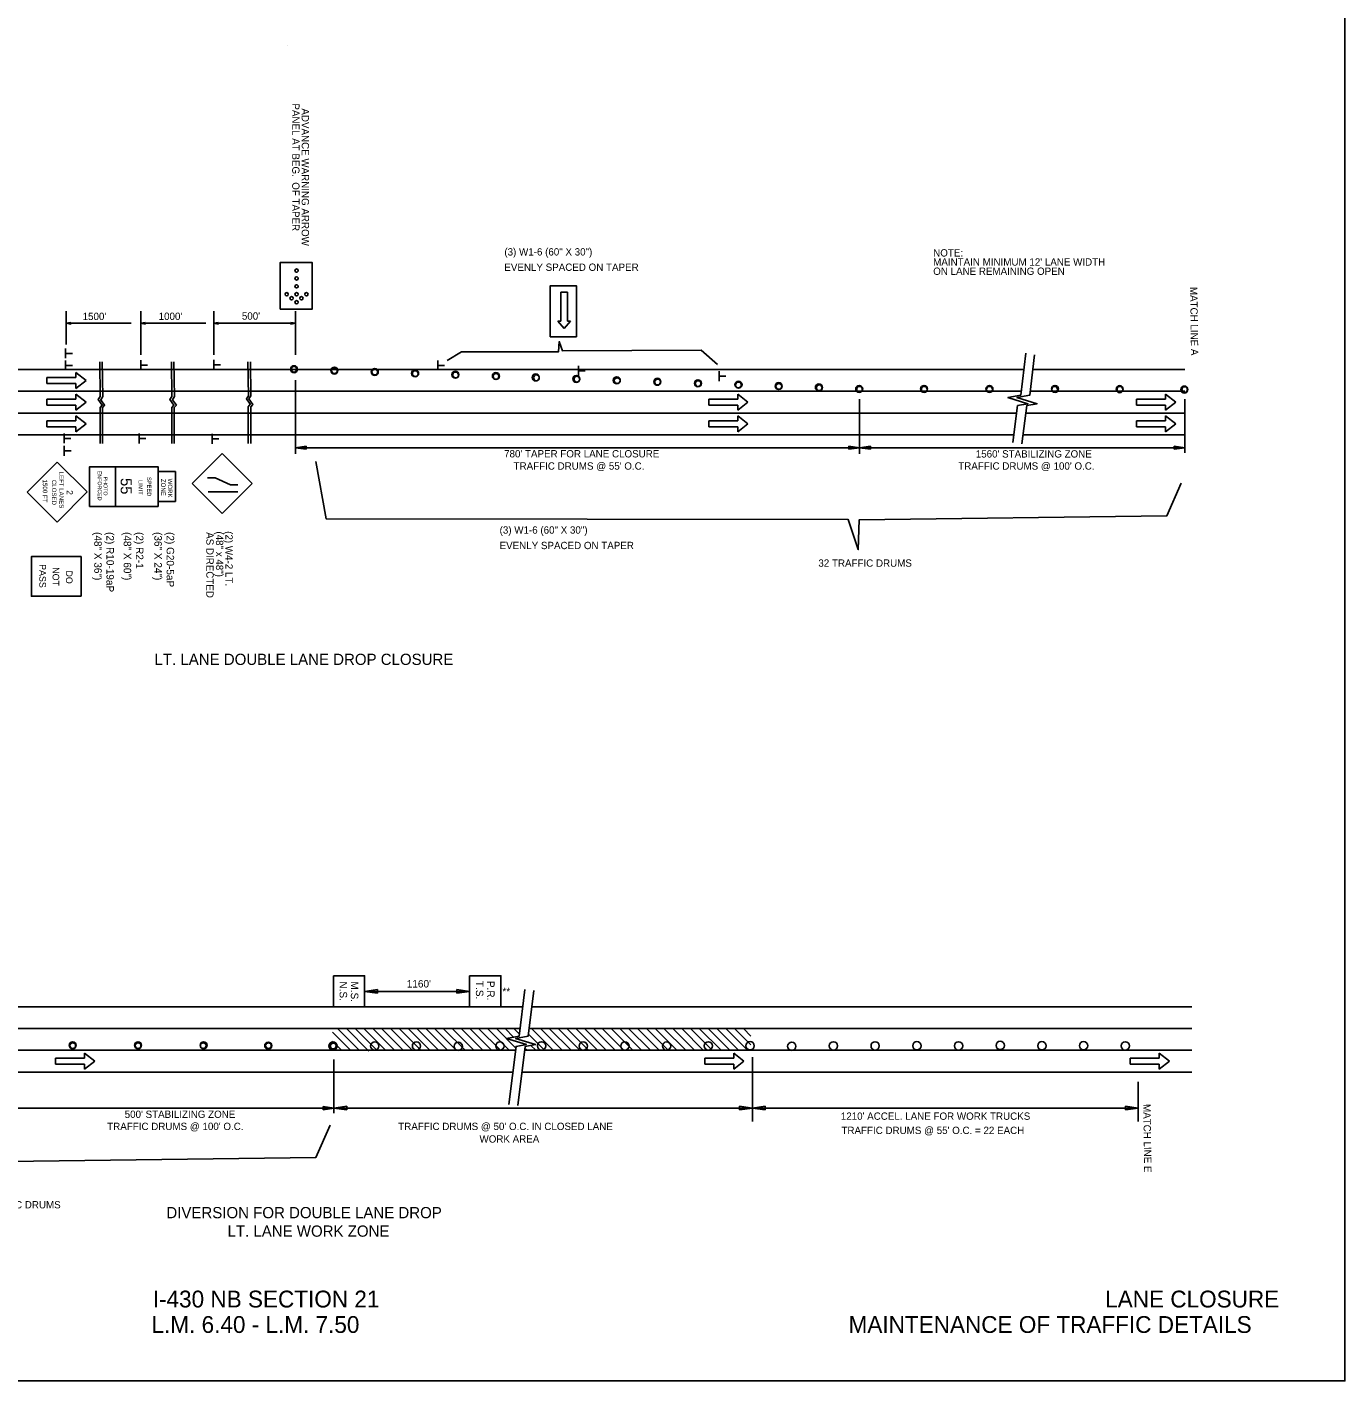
# Model space of a CAD drawing. Extents: x -100 to 745, y -1581 to -107.
# Drawn here: x 639.2 to 744.8, y -706.8 to -598.3 of the extents above; entities that cross this region are included whole.
import ezdxf

# ---------------------------------------------------------------- set-up
doc = ezdxf.new("R2010")
doc.units = 0
for name, color, linetype in [('Default', 7, 'Continuous'), ('R_Border', 7, 'Continuous'), ('R_Proposed Road', 7, 'Continuous'), ('R_ROW', 7, 'Continuous'), ('R_ROW Annot', 7, 'Continuous')]:
    doc.layers.add(name, color=color, linetype=linetype)

msp = doc.modelspace()

# ---------------------------------------------------------------- linework, layer by layer
at = {"layer": 'Default'}
for p, q in [((681.95, -619.54), (681.95, -621.87)), ((681.95, -619.54), (682.47, -619.54)), ((682.47, -619.54), (682.47, -621.87)), ((642.31, -621.05), (642.31, -623.74)), ((648.28, -621.05), (648.28, -624.57)), ((654.13, -621.05), (654.13, -624.57)), ((660.68, -621.05), (660.68, -624.57)), ((642.68, -621.98), (642.31, -622.03)), ((642.31, -622.03), (647.53, -622.03)), ((642.68, -622.09), (642.31, -622.03)), ((642.68, -621.99), (642.37, -622.03)), ((642.68, -622.08), (642.37, -622.03)), ((642.68, -622), (642.43, -622.03)), ((642.68, -622.07), (642.43, -622.03)), ((642.68, -622), (642.5, -622.03)), ((642.68, -622.06), (642.5, -622.03)), ((642.68, -622.01), (642.56, -622.03)), ((642.68, -622.05), (642.56, -622.03)), ((642.68, -622.02), (642.62, -622.03)), ((642.68, -622.04), (642.62, -622.03)), ((642.68, -622.09), (642.68, -621.98)), ((648.65, -621.98), (648.28, -622.03)), ((648.28, -622.03), (653.5, -622.03)), ((648.65, -622.09), (648.28, -622.03)), ((648.65, -621.99), (648.34, -622.03)), ((648.65, -622.08), (648.34, -622.03)), ((648.65, -622), (648.4, -622.03)), ((648.65, -622.07), (648.4, -622.03)), ((648.65, -622), (648.47, -622.03)), ((648.65, -622.06), (648.47, -622.03)), ((648.65, -622.01), (648.53, -622.03)), ((648.65, -622.05), (648.53, -622.03)), ((648.65, -622.02), (648.59, -622.03)), ((648.65, -622.04), (648.59, -622.03)), ((648.65, -622.09), (648.65, -621.98)), ((654.5, -621.98), (654.13, -622.03)), ((654.13, -622.03), (660.68, -622.03)), ((654.5, -622.09), (654.13, -622.03)), ((654.5, -621.99), (654.19, -622.03)), ((654.5, -622.08), (654.19, -622.03)), ((654.5, -622), (654.25, -622.03)), ((654.5, -622.07), (654.25, -622.03)), ((654.5, -622), (654.32, -622.03)), ((654.5, -622.06), (654.32, -622.03)), ((654.5, -622.01), (654.38, -622.03)), ((654.5, -622.05), (654.38, -622.03)), ((654.5, -622.02), (654.44, -622.03)), ((654.5, -622.04), (654.44, -622.03)), ((654.5, -622.09), (654.5, -621.98)), ((660.3, -621.98), (660.68, -622.03)), ((660.3, -621.98), (660.3, -622.09)), ((660.3, -621.99), (660.61, -622.03)), ((660.3, -622), (660.55, -622.03)), ((660.3, -622), (660.49, -622.03)), ((660.3, -622.01), (660.42, -622.03)), ((660.3, -622.02), (660.36, -622.03)), ((660.3, -622.09), (660.68, -622.03)), ((660.3, -622.05), (660.42, -622.03)), ((660.3, -622.07), (660.55, -622.03)), ((660.3, -622.08), (660.61, -622.03)), ((660.3, -622.06), (660.49, -622.03)), ((660.3, -622.04), (660.36, -622.03)), ((681.95, -621.87), (681.7, -621.87)), ((681.7, -621.87), (682.21, -622.44)), ((682.21, -622.44), (682.73, -621.87)), ((682.47, -621.87), (682.73, -621.87)), ((642.27, -624.82), (642.27, -624.04)), ((642.28, -624.44), (642.82, -624.44)), ((636.02, -625.74), (644.68, -625.74)), ((642.27, -625.79), (642.27, -625.01)), ((642.28, -625.4), (642.81, -625.4)), ((643.09, -625.98), (643.09, -626.38)), ((643.09, -625.98), (643.91, -626.61)), ((644.68, -625.74), (660.68, -625.74)), ((648.28, -625.77), (648.28, -624.99)), ((648.29, -625.38), (648.82, -625.38)), ((654.13, -625.75), (654.13, -624.97)), ((654.14, -625.36), (654.67, -625.36)), ((660.68, -625.74), (719.03, -625.74)), ((672.08, -625.02), (672.08, -625.8)), ((672.09, -625.41), (672.62, -625.41)), ((683.35, -625.45), (683.35, -626.23)), ((683.36, -625.84), (683.89, -625.84)), ((694.62, -625.88), (694.62, -626.66)), ((719.76, -625.74), (731.95, -625.74)), ((643.09, -626.38), (640.76, -626.38)), ((640.76, -626.38), (640.76, -626.85)), ((643.09, -626.85), (640.76, -626.85)), ((643.91, -626.61), (643.09, -627.25)), ((643.09, -626.85), (643.09, -627.25)), ((660.68, -626.59), (660.68, -632.5)), ((694.63, -626.26), (695.16, -626.26)), ((636.02, -627.48), (644.68, -627.48)), ((643.09, -628.12), (640.76, -628.12)), ((640.76, -628.12), (640.76, -628.59)), ((643.09, -627.72), (643.09, -628.12)), ((643.09, -627.72), (643.91, -628.35)), ((644.68, -627.48), (660.68, -627.48)), ((660.68, -627.48), (718.82, -627.48)), ((696.12, -628.12), (693.79, -628.12)), ((693.79, -628.59), (693.79, -628.12)), ((696.12, -628.12), (696.12, -627.72)), ((696.94, -628.35), (696.12, -627.72)), ((705.88, -632.5), (705.88, -628.11)), ((719.55, -627.48), (731.95, -627.48)), ((730.39, -628.12), (728.07, -628.12)), ((728.07, -628.59), (728.07, -628.12)), ((730.39, -628.12), (730.39, -627.72)), ((731.21, -628.35), (730.39, -627.72)), ((731.95, -632.41), (731.95, -628.11)), ((636.02, -629.22), (644.68, -629.22)), ((643.09, -628.59), (640.76, -628.59)), ((643.91, -628.35), (643.09, -628.98)), ((643.09, -628.59), (643.09, -628.98)), ((644.68, -629.22), (660.68, -629.22)), ((660.68, -629.22), (718.47, -629.22)), ((696.12, -628.59), (693.79, -628.59)), ((696.12, -628.98), (696.94, -628.35)), ((696.12, -628.98), (696.12, -628.59)), ((719.2, -629.22), (731.95, -629.22)), ((730.39, -628.59), (728.07, -628.59)), ((730.39, -628.98), (731.21, -628.35)), ((730.39, -628.98), (730.39, -628.59)), ((643.09, -629.85), (640.76, -629.85)), ((640.76, -629.85), (640.76, -630.33)), ((643.09, -630.33), (640.76, -630.33)), ((643.09, -629.46), (643.09, -629.85)), ((643.09, -629.46), (643.91, -630.09)), ((643.91, -630.09), (643.09, -630.72)), ((643.09, -630.33), (643.09, -630.72)), ((696.12, -629.85), (693.79, -629.85)), ((693.79, -630.33), (693.79, -629.85)), ((696.12, -630.33), (693.79, -630.33)), ((696.12, -629.85), (696.12, -629.46)), ((696.94, -630.09), (696.12, -629.46)), ((696.12, -630.72), (696.94, -630.09)), ((696.12, -630.72), (696.12, -630.33)), ((730.39, -629.85), (728.07, -629.85)), ((728.07, -630.33), (728.07, -629.85)), ((730.39, -630.33), (728.07, -630.33)), ((730.39, -629.85), (730.39, -629.46)), ((731.21, -630.09), (730.39, -629.46)), ((730.39, -630.72), (731.21, -630.09)), ((730.39, -630.72), (730.39, -630.33)), ((636.02, -630.96), (645.6, -630.96)), ((642.14, -631.64), (642.14, -630.85)), ((642.15, -631.25), (642.69, -631.25)), ((644.68, -630.96), (660.68, -630.96)), ((648.15, -631.66), (648.15, -630.87)), ((648.16, -631.27), (648.7, -631.27)), ((654, -631.68), (654, -630.9)), ((654.01, -631.29), (654.55, -631.29)), ((660.68, -630.96), (718.25, -630.96)), ((718.98, -630.96), (731.95, -630.96)), ((642.15, -632.64), (642.15, -631.86)), ((642.16, -632.25), (642.7, -632.25)), ((654.81, -632.46), (652.4, -634.87)), ((654.81, -632.46), (657.22, -634.87)), ((661.54, -631.87), (660.68, -632)), ((705.88, -632), (660.68, -632)), ((660.68, -632), (661.54, -632.13)), ((661.54, -632.13), (661.54, -631.87)), ((705.88, -632), (705.01, -631.87)), ((705.01, -631.87), (705.01, -632.13)), ((705.01, -632.13), (705.88, -632)), ((706.75, -631.87), (705.88, -632)), ((731.95, -632), (705.88, -632)), ((705.88, -632), (706.75, -632.13)), ((706.75, -632.13), (706.75, -631.87)), ((731.95, -632), (731.08, -631.87)), ((731.08, -631.87), (731.08, -632.13)), ((731.08, -632.13), (731.95, -632)), ((639.18, -635.56), (641.59, -633.15)), ((643.99, -635.55), (641.59, -633.15)), ((653.64, -634.41), (654.26, -634.41)), ((654.26, -634.41), (655.48, -634.97)), ((641.59, -637.96), (639.18, -635.56)), ((641.59, -637.96), (643.99, -635.55)), ((652.4, -634.87), (654.81, -637.28)), ((653.7, -635.54), (656.07, -635.54)), ((657.22, -634.87), (654.81, -637.28)), ((655.48, -634.97), (656.07, -634.97)), ((666.22, -675.57), (667.25, -675.41)), ((674.64, -675.57), (666.22, -675.57)), ((667.25, -675.72), (666.22, -675.57)), ((667.25, -675.41), (667.25, -675.72)), ((673.61, -675.72), (673.61, -675.41)), ((673.61, -675.41), (674.64, -675.57)), ((674.64, -675.57), (673.61, -675.72)), ((619.84, -676.82), (678.89, -676.82)), ((679.62, -676.82), (732.51, -676.82)), ((620.05, -678.55), (678.68, -678.55)), ((663.64, -678.85), (665.08, -680.29)), ((664.05, -678.55), (665.79, -680.29)), ((664.76, -678.55), (666.55, -680.35)), ((665.46, -678.55), (667.2, -680.29)), ((666.17, -678.55), (667.91, -680.29)), ((666.88, -678.55), (668.61, -680.29)), ((667.58, -678.55), (669.32, -680.29)), ((668.29, -678.55), (670.03, -680.29)), ((669, -678.55), (670.74, -680.29)), ((669.7, -678.55), (671.44, -680.29)), ((670.41, -678.55), (672.15, -680.29)), ((671.12, -678.55), (672.86, -680.29)), ((671.83, -678.55), (673.56, -680.29)), ((672.53, -678.55), (674.27, -680.29)), ((673.24, -678.55), (674.98, -680.29)), ((673.95, -678.55), (675.69, -680.29)), ((674.65, -678.55), (676.39, -680.29)), ((675.36, -678.55), (677.1, -680.29)), ((676.07, -678.55), (677.81, -680.29)), ((676.78, -678.55), (678.35, -680.12)), ((677.48, -678.55), (678.16, -679.23)), ((678.19, -678.55), (678.63, -678.99)), ((679.35, -679.01), (680.64, -680.29)), ((679.41, -678.55), (732.51, -678.55)), ((679.6, -678.55), (681.34, -680.29)), ((680.31, -678.55), (682.05, -680.29)), ((681.02, -678.55), (682.76, -680.29)), ((681.73, -678.55), (683.46, -680.29)), ((682.43, -678.55), (684.17, -680.29)), ((683.14, -678.55), (684.88, -680.29)), ((683.85, -678.55), (685.59, -680.29)), ((684.55, -678.55), (686.29, -680.29)), ((685.26, -678.55), (687, -680.29)), ((685.97, -678.55), (687.71, -680.29)), ((686.68, -678.55), (688.41, -680.29)), ((687.38, -678.55), (689.12, -680.29)), ((688.09, -678.55), (689.83, -680.29)), ((688.8, -678.55), (690.54, -680.29)), ((689.5, -678.55), (691.24, -680.29)), ((690.21, -678.55), (691.95, -680.29)), ((690.92, -678.55), (692.66, -680.29)), ((691.63, -678.55), (693.36, -680.29)), ((692.33, -678.55), (694.07, -680.29)), ((693.04, -678.55), (694.78, -680.29)), ((693.75, -678.55), (695.48, -680.29)), ((694.45, -678.55), (696.19, -680.29)), ((695.16, -678.55), (696.9, -680.29)), ((695.87, -678.55), (697.17, -679.86)), ((696.57, -678.55), (697.17, -679.15)), ((663.64, -679.56), (664.37, -680.29)), ((679.07, -680.14), (679.22, -680.29)), ((679.53, -679.9), (679.93, -680.29)), ((620.41, -680.29), (678.32, -680.29)), ((643.78, -680.92), (641.46, -680.92)), ((641.46, -681.4), (641.46, -680.92)), ((643.78, -680.92), (643.78, -680.53)), ((644.6, -681.16), (643.78, -680.53)), ((643.78, -681.79), (644.6, -681.16)), ((663.76, -685.33), (663.76, -681.03)), ((679.05, -680.29), (732.51, -680.29)), ((695.8, -680.92), (693.48, -680.92)), ((693.48, -681.4), (693.48, -680.92)), ((695.8, -680.92), (695.8, -680.53)), ((696.62, -681.16), (695.8, -680.53)), ((695.8, -681.79), (696.62, -681.16)), ((697.3, -686), (697.3, -680.85)), ((729.89, -680.92), (727.56, -680.92)), ((727.56, -681.4), (727.56, -680.92)), ((729.89, -680.92), (729.89, -680.53)), ((730.71, -681.16), (729.89, -680.53)), ((729.89, -681.79), (730.71, -681.16)), ((619.89, -682.03), (678.11, -682.03)), ((643.78, -681.4), (641.46, -681.4)), ((643.78, -681.79), (643.78, -681.4)), ((678.84, -682.03), (732.51, -682.03)), ((695.8, -681.4), (693.48, -681.4)), ((695.8, -681.79), (695.8, -681.4)), ((729.89, -681.4), (727.56, -681.4)), ((729.89, -681.79), (729.89, -681.4)), ((728.21, -686), (728.21, -682.81)), ((663.76, -684.92), (637.68, -684.92)), ((663.76, -684.92), (662.89, -684.79)), ((662.89, -684.79), (662.89, -685.05)), ((662.89, -685.05), (663.76, -684.92)), ((664.79, -684.76), (663.76, -684.92)), ((697.3, -684.92), (663.76, -684.92)), ((663.76, -684.92), (664.79, -685.07)), ((664.79, -685.07), (664.79, -684.76)), ((697.3, -684.92), (696.26, -684.76)), ((696.26, -684.76), (696.26, -685.07)), ((696.26, -685.07), (697.3, -684.92)), ((698.33, -684.76), (697.3, -684.92)), ((728.21, -684.92), (697.3, -684.92)), ((697.3, -684.92), (698.33, -685.07)), ((698.33, -685.07), (698.33, -684.76)), ((728.21, -684.92), (727.18, -684.76)), ((727.18, -684.76), (727.18, -685.07)), ((727.18, -685.07), (728.21, -684.92))]:
    msp.add_line(p, q, dxfattribs=at)
for points in [[(659.45, -620.89), (659.45, -617.17), (662.03, -617.17), (662.03, -620.89)], [(681.1, -623.11), (681.1, -619.02), (683.19, -619.02), (683.19, -623.11)], [(646.27, -636.7), (644.19, -636.7), (644.19, -633.53), (646.27, -633.53)], [(649.68, -636.7), (646.27, -636.7), (646.27, -633.53), (649.68, -633.53)], [(651.07, -636.3), (649.68, -636.3), (649.68, -633.92), (651.07, -633.92)], [(643.51, -643.9), (639.52, -643.9), (639.52, -640.73), (643.51, -640.73)], [(663.72, -674.32), (666.22, -674.32), (666.22, -676.82), (663.72, -676.82)], [(674.64, -674.32), (677.14, -674.32), (677.14, -676.82), (674.64, -676.82)]]:
    msp.add_lwpolyline(points, close=True, dxfattribs=at)
for points in [[(672.83, -625), (673.99, -624.32), (681.75, -624.32), (681.82, -623.5), (682.09, -624.25), (693.2, -624.18), (694.49, -625.34)], [(718.17, -631.59), (718.54, -628.62), (719.37, -628.48), (717.77, -627.99), (718.79, -627.8), (719.19, -624.43)], [(718.89, -631.68), (719.27, -628.62), (720.1, -628.48), (718.49, -627.99), (719.51, -627.8), (719.9, -624.56)], [(645, -625.13), (645.04, -627.91), (644.88, -628.15), (645.19, -628.58), (645.03, -628.78), (645.03, -631.67)], [(645.2, -625.13), (645.24, -627.91), (645.08, -628.16), (645.39, -628.59), (645.23, -628.79), (645.23, -631.67)], [(650.74, -625.13), (650.79, -627.91), (650.62, -628.15), (650.94, -628.58), (650.77, -628.78), (650.77, -631.67)], [(650.94, -625.13), (650.99, -627.91), (650.82, -628.16), (651.14, -628.59), (650.97, -628.79), (650.97, -631.67)], [(656.87, -625.13), (656.91, -627.84), (656.75, -628.08), (657.06, -628.52), (656.9, -628.72), (656.9, -631.67)], [(657.07, -625.13), (657.11, -627.85), (656.95, -628.09), (657.26, -628.53), (657.1, -628.73), (657.1, -631.67)], [(662.31, -633.1), (663.14, -637.7), (704.96, -637.75), (705.77, -640.17), (705.84, -637.79), (730.51, -637.45), (731.65, -634.85)], [(677.78, -684.63), (678.36, -679.98), (679.19, -679.83), (677.59, -679.34), (678.61, -679.15), (679.06, -675.42)], [(678.5, -684.72), (679.09, -679.98), (679.92, -679.83), (678.32, -679.34), (679.34, -679.15), (679.77, -675.5)], [(592.97, -686.51), (594.94, -689.12), (636.77, -689.17), (637.58, -691.59), (637.65, -689.21), (662.32, -688.87), (663.46, -686.28)]]:
    msp.add_lwpolyline(points, dxfattribs=at)
for centre, radius in [((660.77, -617.81), 0.131), ((660.77, -618.44), 0.131), ((660.77, -619.07), 0.131), ((659.98, -619.7), 0.131), ((660.37, -620.02), 0.131), ((660.77, -619.7), 0.131), ((660.77, -620.34), 0.131), ((661.16, -620.02), 0.131), ((661.56, -619.7), 0.131), ((660.57, -625.71), 0.281), ((660.56, -625.71), 0.229), ((660.57, -625.71), 0.229), ((663.8, -625.82), 0.281), ((663.8, -625.83), 0.229), ((667.04, -625.93), 0.281), ((667.04, -625.94), 0.229), ((670.27, -626.04), 0.281), ((670.28, -626.06), 0.229), ((673.5, -626.15), 0.281), ((673.51, -626.17), 0.229), ((676.74, -626.26), 0.281), ((676.75, -626.29), 0.229), ((679.93, -626.37), 0.281), ((679.99, -626.4), 0.229), ((683.18, -626.49), 0.281), ((683.23, -626.51), 0.229), ((686.43, -626.6), 0.281), ((686.46, -626.63), 0.229), ((689.68, -626.72), 0.281), ((689.7, -626.74), 0.229), ((692.93, -626.84), 0.281), ((692.94, -626.86), 0.229), ((696.18, -626.95), 0.281), ((696.17, -626.97), 0.229), ((699.4, -627.06), 0.281), ((699.41, -627.09), 0.229), ((702.62, -627.17), 0.281), ((702.65, -627.2), 0.229), ((705.85, -627.29), 0.281), ((705.88, -627.32), 0.229), ((711.05, -627.29), 0.281), ((711.06, -627.32), 0.229), ((716.29, -627.29), 0.281), ((716.29, -627.32), 0.229), ((721.54, -627.29), 0.281), ((721.51, -627.32), 0.229), ((726.72, -627.31), 0.281), ((726.74, -627.32), 0.229), ((731.91, -627.34), 0.281), ((705.87, -627.32), 0.229), ((731.93, -627.34), 0.229), ((642.83, -679.89), 0.281), ((642.84, -679.92), 0.229), ((648.07, -679.89), 0.281), ((648.07, -679.92), 0.229), ((653.32, -679.89), 0.281), ((653.29, -679.92), 0.229), ((658.5, -679.92), 0.281), ((658.52, -679.92), 0.229), ((663.69, -679.95), 0.333), ((663.69, -679.95), 0.281), ((663.71, -679.95), 0.229), ((667.04, -679.95), 0.333), ((670.38, -679.95), 0.333), ((673.72, -679.97), 0.333), ((677.06, -679.95), 0.333), ((680.4, -679.94), 0.333), ((683.74, -679.95), 0.333), ((687.08, -679.95), 0.333), ((690.42, -679.95), 0.333), ((693.76, -679.94), 0.333), ((697.11, -679.93), 0.333), ((700.45, -679.97), 0.333), ((703.79, -679.94), 0.333), ((707.13, -679.94), 0.333), ((710.47, -679.93), 0.333), ((713.81, -679.94), 0.333), ((717.15, -679.9), 0.333), ((720.49, -679.93), 0.333), ((723.83, -679.92), 0.333), ((727.17, -679.94), 0.333)]:
    msp.add_circle(centre, radius, dxfattribs=at)
at = {"layer": 'R_Proposed Road'}
msp.add_lwpolyline([(574.77, -596.79), (574.77, -706.79), (744.77, -706.79), (744.77, -596.79)], close=True, dxfattribs=at)
at = {"layer": 'R_ROW Annot'}
msp.add_line((660.05, -599.8), (660.05, -599.8), dxfattribs=at)

# ---------------------------------------------------------------- texts
at = {"layer": 'Default'}
for s, height, rotation, p in [('PANEL AT BEG.  OF TAPER', 0.5862, 270, (660.42, -604.41)), ('ADVANCE WARNING ARROW', 0.5862, 270, (661.18, -604.81)), ('(3) W1-6 (60" X 30")', 0.5862, 0.0075, (677.42, -616.6)), ('EVENLY SPACED ON TAPER', 0.5862, 0.0075, (677.42, -617.83)), ('MATCH LINE A', 0.5862, 270.8059, (732.36, -619.12)), ('1500 FT', 0.357, 270.0006, (640.44, -634.55)), ('CLOSED', 0.354, 270.1003, (641.17, -634.58)), ('LEFT LANES', 0.354, 270.1004, (641.76, -633.92)), ('ENFORCED', 0.308, 270.0872, (644.84, -633.85)), ('PHOTO', 0.308, 270.0872, (645.31, -634.32)), ('55', 0.885, 270, (646.68, -634.43)), ('LIMIT', 0.33, 270, (648.12, -634.6)), ('SPEED', 0.33, 270, (648.8, -634.35)), ('ZONE', 0.354, 270.1004, (649.92, -634.5)), ('WORK', 0.354, 270.1004, (650.46, -634.48)), ('2', 0.5, 270, (642.35, -635.41)), ('(48" X 36")', 0.6, 270, (644.56, -638.76)), ('(2) R10-19aP', 0.6, 270, (645.54, -638.76)), ('(48" X 60")', 0.6, 270, (646.92, -638.76)), ('(2) R2-1', 0.6, 270, (647.9, -638.76)), ('(36" X 24")', 0.6, 270, (649.38, -638.76)), ('(2) G20-5aP', 0.6, 270, (650.36, -638.76)), ('AS DIRECTED ', 0.5862, 270, (653.54, -638.77)), ('(48" x 48")', 0.5862, 270, (654.31, -638.71)), ('(2) W4-2 LT.', 0.5862, 270, (655.07, -638.69)), ('(3) W1-6 (60" X 30")', 0.5862, 0.0075, (677.04, -638.89)), ('EVENLY SPACED ON TAPER', 0.5862, 0.0075, (677.04, -640.13)), ('PASS', 0.532, 270, (640.16, -641.33)), ('NOT', 0.532, 270, (641.22, -641.58)), ('DO', 0.532, 270, (642.29, -641.84)), ('T.S.', 0.6, 270, (675.14, -674.73)), ('P.R.', 0.6, 270, (676.04, -674.73)), ('N.S.', 0.6, 270, (664.22, -674.77)), ('M.S.', 0.6, 270, (665.12, -674.77)), ('MATCH LINE E', 0.5862, 270.8059, (728.61, -684.6))]:
    msp.add_text(s, height=height, rotation=rotation, dxfattribs=at).set_placement(p)
for s, height, p in [('NOTE:', 0.586, (711.78, -616.68)), ("MAINTAIN MINIMUM 12' LANE WIDTH", 0.5862, (711.78, -617.41)), ('ON LANE REMAINING OPEN', 0.5862, (711.78, -618.15)), ("1500'", 0.586, (643.63, -621.77)), ("1000'", 0.586, (649.72, -621.76)), ("500'", 0.586, (656.39, -621.74)), ("780' TAPER FOR LANE CLOSURE", 0.5862, (677.4, -632.78)), ("1560' STABILIZING ZONE", 0.5862, (715.19, -632.79)), ("TRAFFIC DRUMS @ 55' O.C.", 0.5862, (678.16, -633.76)), ("TRAFFIC DRUMS @ 100' O.C.", 0.5862, (713.79, -633.76)), ('32 TRAFFIC DRUMS', 0.5862, (702.58, -641.54)), ("1160'", 0.6, (669.6, -675.26)), ('**', 0.6, (677.26, -675.87)), ("500' STABILIZING ZONE", 0.5862, (647, -685.71)), ("1210' ACCEL. LANE FOR WORK TRUCKS", 0.5862, (704.38, -685.86)), ("TRAFFIC DRUMS @ 100' O.C.", 0.5862, (645.6, -686.68)), ("TRAFFIC DRUMS @ 50' O.C. IN CLOSED LANE", 0.5862, (668.92, -686.68)), ("TRAFFIC DRUMS @ 55' O.C. = 22 EACH", 0.5862, (704.43, -687)), ('WORK AREA', 0.586, (675.43, -687.69)), ('19 TRAFFIC DRUMS', 0.5862, (634.38, -692.96))]:
    msp.add_text(s, height=height, dxfattribs=at).set_placement(p)
at = {"layer": 'R_Border'}
for s, p in [('I-430 NB SECTION 21', (649.25, -700.9)), ('LANE CLOSURE', (725.56, -700.9)), ('L.M. 6.40 - L.M. 7.50', (649.15, -702.94)), ('MAINTENANCE OF TRAFFIC DETAILS', (705, -702.94))]:
    msp.add_text(s, height=1.35, dxfattribs=at).set_placement(p)
at = {"layer": 'R_ROW'}
for s, p in [('LT. LANE DOUBLE LANE DROP CLOSURE', (649.39, -649.41)), ('DIVERSION FOR DOUBLE LANE DROP', (650.34, -693.75)), ('LT. LANE WORK ZONE', (655.24, -695.23))]:
    msp.add_text(s, height=0.9, dxfattribs=at).set_placement(p)

doc.saveas('drawing.dxf')
